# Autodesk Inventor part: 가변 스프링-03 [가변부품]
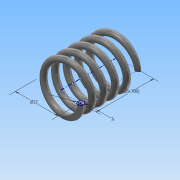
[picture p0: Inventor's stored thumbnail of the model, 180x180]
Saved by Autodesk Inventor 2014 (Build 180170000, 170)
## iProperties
Created: 2015-09
Part Number: 가변 스프링-03 [가변부품]
Material: 강철, 탄소
Document SubType Name: Modeling
Designer: study
Density: 1 g/cm^3
Appearance: 반연마
Author: study
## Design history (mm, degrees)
sketch "스케치1"
  geometry: L1 (0, 0)-(11, 0); L2 (11, 0)-(11, 29.708); L3 (11, 29.708)-(0, 29.708); L4 (0, 29.708)-(0, 0); C1 r 1.5 at (11, 0)
  constraints: 8 end point, 2 parallel, 1 centre point, 1 coincident, 1 horizontal, 1 perpendicular
  dimensions: "d0" = 22 diameter of L2 L4; "d1" = 3 diameter of C1; "d2" = 29.70829 distance between parallel lines of L3 L1 (derived)
feature "코일1" sketch "스케치1" pitch "d3" = 10; turns "d5" = 5; dims "d4" = 29.70829 (= d2), "d6" = 0, angle "d7" = 90 deg, angle "d8" = 90 deg, "d9" = 0, "d10" = 0
node "작업 평면1"
sketch "스케치2"
  geometry: L1 (-12.5, 0)-(-9.5, 0) reference; 1 further point
  constraints: 1 horizontal alignment
extrude "돌출1" cut sketch "스케치2" stored distance "d12" = 10; taper "d13" = 0 deg
node "작업 평면2"
sketch "스케치3"
  geometry: L1 (-9.5, 0)-(-12.5, 0) reference; L2 (-9.5, 0)-(-12.5, 0) reference; 1 further point
  constraints: 2 horizontal alignment
extrude "돌출2" cut sketch "스케치3" stored distance "d15" = 10; taper "d16" = 0 deg
node "솔리드1"
node "절단 모서리 투영1"
node "절단 모서리 투영2"
node "절단 모서리 투영3"
other parameters: "d11" = 0, "d14" = 29.70829 (= d2)
